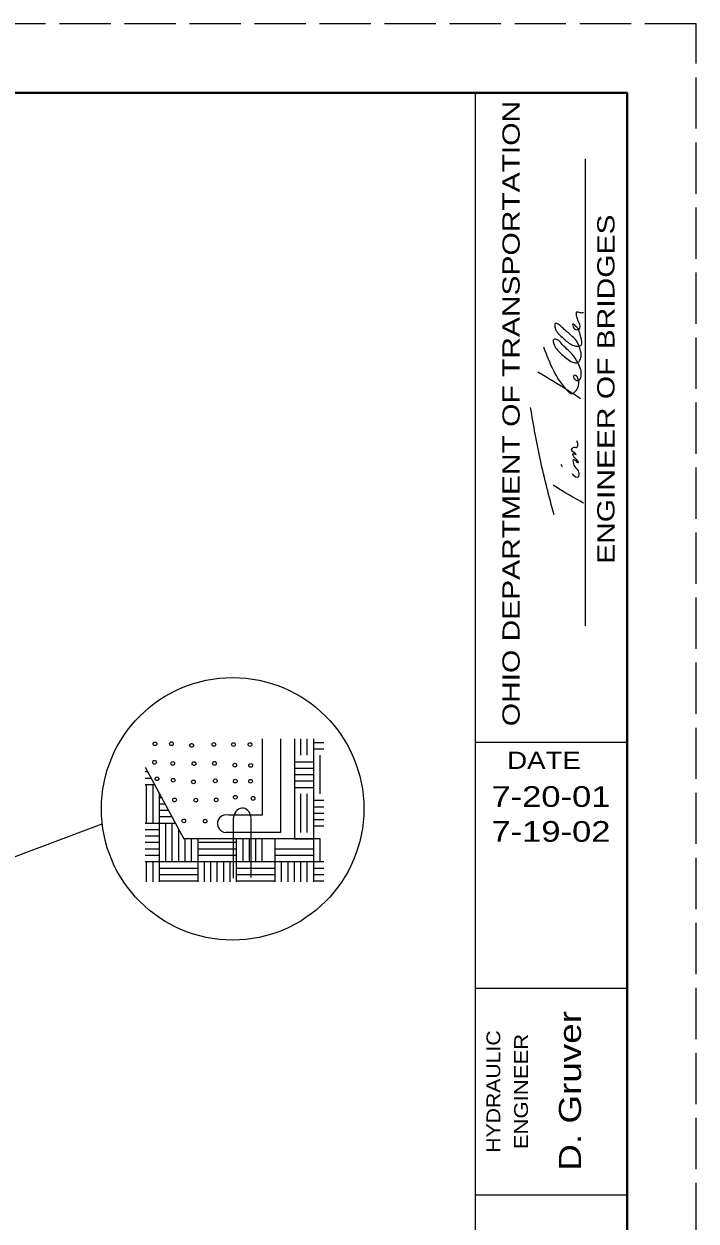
# Model space of a CAD drawing. Extents: x 1083.1 to 1117.1, y 719.4 to 741.4.
# Drawn here: x 1112.25 to 1117.13, y 732.67 to 741.35 of the extents above; entities that cross this region are included whole.
import ezdxf
from ezdxf.enums import TextEntityAlignment as Align

# ---------------------------------------------------------------- set-up
doc = ezdxf.new("R2010")
doc.units = 0
doc.header["$LTSCALE"] = 0.062
doc.linetypes.add('LONG_DASHED', pattern=[7.5, 6, -1.5])
doc.layers.add('1', color=7, linetype='Continuous', lineweight=13)

msp = doc.modelspace()

# ---------------------------------------------------------------- linework, layer by layer
at = {"layer": '1', "lineweight": 25}
for p, q in [((1085.12642, 740.85408), (1116.62642, 740.85408)), ((1115.52642, 719.85408), (1115.52642, 740.85408)), ((1116.62642, 740.85408), (1116.62642, 719.85408)), ((1116.62642, 736.13825), (1115.52642, 736.13825)), ((1108.8655, 734.06875), (1112.81717, 735.54867)), ((1113.7685, 735.58275), (1113.7685, 735.15425)), ((1113.89717, 735.15925), (1113.89717, 735.59258)), ((1116.62642, 734.35408), (1115.52642, 734.35408)), ((1116.62642, 732.85408), (1115.52642, 732.85408))]:
    msp.add_line(p, q, dxfattribs=at)
at = {"layer": '1'}
for p, q in [((1116.32517, 736.98508), (1116.32517, 740.37517)), ((1116.15767, 738.136), (1116.1475, 738.15525)), ((1113.97767, 736.16442), (1113.97767, 735.61058)), ((1114.112, 736.16442), (1114.112, 735.48542)), ((1114.212, 736.16442), (1114.212, 735.43958)), ((1114.25867, 736.04592), (1114.25867, 736.16442)), ((1114.30533, 736.04592), (1114.30533, 736.16442)), ((1114.352, 735.43958), (1114.352, 736.16442)), ((1114.352, 736.13925), (1114.42483, 736.13925)), ((1114.352, 736.09258), (1114.42483, 736.09258)), ((1114.39867, 735.76608), (1114.39867, 736.04592)), ((1113.12783, 735.95925), (1113.41, 735.43958)), ((1114.212, 735.99925), (1114.352, 735.99925)), ((1113.12783, 735.92708), (1113.14533, 735.92708)), ((1113.12783, 735.88042), (1113.17067, 735.88042)), ((1114.212, 735.95275), (1114.352, 735.95275)), ((1114.212, 735.90608), (1114.352, 735.90608)), ((1113.12783, 735.83375), (1113.196, 735.83375)), ((1113.13917, 735.69392), (1113.13917, 735.83375)), ((1113.18583, 735.69392), (1113.18583, 735.83375)), ((1114.212, 735.85942), (1114.352, 735.85942)), ((1114.212, 735.81275), (1114.352, 735.81275)), ((1113.13917, 735.55392), (1113.13917, 735.69392)), ((1113.18583, 735.55392), (1113.18583, 735.69392)), ((1113.2325, 735.12642), (1113.2325, 735.76642)), ((1113.2325, 735.74042), (1113.24667, 735.74042)), ((1113.2325, 735.69392), (1113.272, 735.69392)), ((1114.25867, 735.62625), (1114.25867, 735.76608)), ((1114.30533, 735.62625), (1114.30533, 735.76608)), ((1114.352, 735.71942), (1114.42483, 735.71942)), ((1113.2325, 735.64725), (1113.29733, 735.64725)), ((1113.97767, 735.61058), (1113.736, 735.61058)), ((1114.25867, 735.48625), (1114.25867, 735.62625)), ((1114.30533, 735.48625), (1114.30533, 735.62625)), ((1114.352, 735.67275), (1114.42483, 735.67275)), ((1114.352, 735.62625), (1114.42483, 735.62625)), ((1113.12783, 735.55392), (1113.348, 735.55392)), ((1113.2325, 735.60058), (1113.32267, 735.60058)), ((1113.27917, 735.27408), (1113.27917, 735.55392)), ((1113.32583, 735.27408), (1113.32583, 735.55392)), ((1114.352, 735.57958), (1114.42483, 735.57958)), ((1114.352, 735.53292), (1114.42483, 735.53292)), ((1113.12783, 735.50725), (1113.2325, 735.50725)), ((1113.12783, 735.46058), (1113.2325, 735.46058)), ((1113.3725, 735.27408), (1113.3725, 735.50875)), ((1113.41917, 735.27408), (1113.41917, 735.43958)), ((1113.46583, 735.27408), (1113.46583, 735.43958)), ((1113.51233, 735.12642), (1113.51233, 735.43958)), ((1114.112, 735.48542), (1113.71467, 735.48542)), ((1113.79233, 735.12642), (1113.79233, 735.43958)), ((1113.83883, 735.27408), (1113.83883, 735.43958)), ((1113.8855, 735.27408), (1113.8855, 735.43958)), ((1113.93217, 735.27408), (1113.93217, 735.43958)), ((1113.97883, 735.27408), (1113.97883, 735.43958)), ((1114.07217, 735.12642), (1114.07217, 735.43958)), ((1114.07217, 735.43358), (1114.07217, 735.43958)), ((1114.212, 735.43958), (1114.352, 735.43958)), ((1114.352, 735.12642), (1114.352, 735.43958)), ((1114.39867, 735.27408), (1114.39867, 735.43958)), ((1113.12783, 735.41408), (1113.2325, 735.41408)), ((1113.12783, 735.36742), (1113.2325, 735.36742)), ((1113.51233, 735.41408), (1113.65233, 735.41408)), ((1113.51233, 735.36742), (1113.65233, 735.36742)), ((1113.65233, 735.41408), (1113.79233, 735.41408)), ((1113.65233, 735.36742), (1113.79233, 735.36742)), ((1114.07133, 735.36742), (1114.352, 735.36742)), ((1113.12783, 735.32075), (1113.2325, 735.32075)), ((1113.12783, 735.27408), (1114.1265, 735.27408)), ((1113.13917, 735.13425), (1113.13917, 735.27408)), ((1113.18583, 735.13425), (1113.18583, 735.27408)), ((1113.51233, 735.32075), (1113.65233, 735.32075)), ((1113.559, 735.13425), (1113.559, 735.27408)), ((1113.60567, 735.13425), (1113.60567, 735.27408)), ((1113.65233, 735.32075), (1113.79233, 735.32075)), ((1113.65233, 735.13425), (1113.65233, 735.27408)), ((1113.699, 735.13425), (1113.699, 735.27408)), ((1113.74567, 735.13425), (1113.74567, 735.27408)), ((1114.075, 735.32075), (1114.352, 735.32075)), ((1114.11883, 735.13425), (1114.11883, 735.27408)), ((1114.1265, 735.27408), (1114.42483, 735.27408)), ((1114.1655, 735.13425), (1114.1655, 735.27408)), ((1114.212, 735.13425), (1114.212, 735.27408)), ((1114.25867, 735.13425), (1114.25867, 735.27408)), ((1114.30533, 735.13425), (1114.30533, 735.27408)), ((1113.2325, 735.22742), (1113.51233, 735.22742)), ((1113.2325, 735.18075), (1113.51233, 735.18075)), ((1113.79233, 735.22742), (1114.07217, 735.22742)), ((1113.79233, 735.18075), (1114.07217, 735.18075)), ((1114.352, 735.22742), (1114.42483, 735.22742)), ((1114.352, 735.18075), (1114.42483, 735.18075)), ((1113.13917, 735.12642), (1113.13917, 735.13425)), ((1113.18583, 735.12642), (1113.18583, 735.13425)), ((1113.2325, 735.13425), (1113.51233, 735.13425)), ((1113.559, 735.12642), (1113.559, 735.13425)), ((1113.60567, 735.12642), (1113.60567, 735.13425)), ((1113.65233, 735.12642), (1113.65233, 735.13425)), ((1113.699, 735.12642), (1113.699, 735.13425)), ((1113.74567, 735.12642), (1113.74567, 735.13425)), ((1113.79233, 735.13425), (1114.07217, 735.13425)), ((1114.11883, 735.12642), (1114.11883, 735.13425)), ((1114.1655, 735.12642), (1114.1655, 735.13425)), ((1114.212, 735.12642), (1114.212, 735.13425)), ((1114.25867, 735.12642), (1114.25867, 735.13425)), ((1114.30533, 735.12642), (1114.30533, 735.13425)), ((1114.352, 735.13425), (1114.42483, 735.13425))]:
    msp.add_line(p, q, dxfattribs=at)
at = {"layer": '1', "linetype": 'LONG_DASHED'}
msp.add_lwpolyline([(1083.12642, 719.35408), (1117.12642, 719.35408), (1117.12642, 741.35408), (1083.12642, 741.35408)], close=True, dxfattribs=at)
at = {"layer": '1', "lineweight": 40}
msp.add_lwpolyline([(1085.12642, 740.85408), (1116.62642, 740.85408), (1116.62642, 719.85408), (1085.12642, 719.85408)], close=True, dxfattribs=at)
msp.add_lwpolyline([(1085.12642, 740.85408), (1116.62642, 740.85408), (1116.62642, 719.85408), (1085.12642, 719.85408)], close=True, dxfattribs=at)
at = {"layer": '1'}
msp.add_lwpolyline([(1114.39867, 735.43958), (1114.1265, 735.43958), (1113.41, 735.43958)], dxfattribs=at)
at = {"layer": '1', "lineweight": 25}
msp.add_circle((1113.76333, 735.65742), 0.9524, dxfattribs=at)
at = {"layer": '1'}
msp.add_arc((1113.71653, 735.5495), 0.06411, 72.32209, 268.34559, dxfattribs=at)
for centre in [(1113.19987, 736.1296), (1113.31948, 736.12993), (1113.46608, 736.11794), (1113.62767, 736.12443), (1113.76977, 736.12343), (1113.88938, 736.12377), (1113.19671, 735.99484), (1113.32915, 735.98651), (1113.48307, 735.98518), (1113.63167, 735.98718), (1113.77927, 735.97418), (1113.89455, 735.97252), (1113.2147, 735.87557), (1113.33248, 735.86491), (1113.63783, 735.86025), (1113.78277, 735.85842), (1113.89338, 735.85709), (1113.47907, 735.85292), (1113.34214, 735.7215), (1113.49607, 735.72016), (1113.64466, 735.72216), (1113.78295, 735.74159), (1113.91163, 735.73309), (1113.40947, 735.5695), (1113.5634, 735.56816)]:
    msp.add_ellipse(centre, major_axis=(0.01346, 0), ratio=0.999895, dxfattribs=at)
at = {"layer": '1', "lineweight": 25}
msp.add_ellipse((1113.83308, 735.58119), major_axis=(0.00198, 0.08195), ratio=0.78812, start_param=4.8785287, end_param=7.8539922, dxfattribs=at)
at = {"layer": '1'}
for points in [[(1116.01825, 739.01108), (1116.20142, 738.68275), (1116.21658, 738.67217), (1116.22675, 738.67217), (1116.25867, 738.69583), (1116.27375, 738.73), (1116.26875, 738.78125), (1116.25183, 738.80308), (1116.23833, 738.80308), (1116.23658, 738.79008), (1116.24675, 738.77492), (1116.26025, 738.7665), (1116.27533, 738.7665), (1116.2905, 738.78808), (1116.29392, 738.80742), (1116.28367, 738.86275), (1116.20142, 738.98317), (1116.15592, 739.02783), (1116.119, 739.06242), (1116.09383, 739.06458), (1116.09558, 739.026), (1116.12075, 738.98725), (1116.188, 738.92492), (1116.23008, 738.8995), (1116.26375, 738.895), (1116.28708, 738.921), (1116.29392, 738.95517), (1116.28883, 738.98092), (1116.25867, 739.05408), (1116.22842, 739.08608), (1116.16783, 739.1395), (1116.13917, 739.16533), (1116.10567, 739.18058), (1116.10225, 739.15258), (1116.11233, 739.12675), (1116.1695, 739.06683), (1116.24017, 739.01958), (1116.29217, 739.02192), (1116.2905, 739.07958), (1116.27867, 739.1225), (1116.26533, 739.14825), (1116.25517, 739.159), (1116.23175, 739.174), (1116.2335, 739.15692), (1116.26875, 739.13542), (1116.28367, 739.14617), (1116.27058, 739.19983), (1116.262, 739.22775), (1116.25867, 739.24042), (1116.25867, 739.25325), (1116.25867, 739.26192), (1116.28367, 739.25975), (1116.30908, 739.25975)], [(1115.97942, 738.82883), (1116.20317, 738.69133), (1116.28883, 738.63567)], [(1116.09567, 737.79183), (1115.997, 738.18708), (1115.92575, 738.56942)], [(1116.22675, 738.09075), (1116.235, 738.08008), (1116.27217, 738.06717), (1116.27692, 738.09958), (1116.25183, 738.136), (1116.23658, 738.17225), (1116.23658, 738.1915), (1116.25183, 738.18525), (1116.262, 738.17442), (1116.27217, 738.17008), (1116.2485, 738.20225), (1116.23658, 738.21725), (1116.2335, 738.23458), (1116.25692, 738.228), (1116.2485, 738.23667), (1116.22333, 738.2645), (1116.2335, 738.27967), (1116.25025, 738.28167), (1116.25867, 738.27967), (1116.26875, 738.301), (1116.262, 738.32892)], [(1116.31083, 737.87625), (1116.10567, 737.99625), (1116.09008, 738.00667)]]:
    msp.add_spline(points, degree=3, dxfattribs=at)

# ---------------------------------------------------------------- texts
for s, height, width, p in [('OHIO DEPARTMENT OF TRANSPORTATION', 0.125, 1.3, (1115.84633, 738.52633)), ('ENGINEER OF BRIDGES', 0.125, 1.3, (1116.53467, 738.70312)), ('D. Gruver', 0.16, 1.25, (1116.2915, 733.61017)), ('HYDRAULIC', 0.1, 1.15, (1115.7055, 733.60517)), ('ENGINEER', 0.1, 1.2, (1115.90642, 733.60521))]:
    msp.add_text(s, height=height, rotation=90, dxfattribs=dict(at, width=width)).set_placement(p, align=Align.CENTER)
for s, height, width, p in [('DATE', 0.125, 1.2, (1116.02312, 735.94683)), ('7-20-01', 0.15, 1.25, (1116.07346, 735.67133)), ('7-19-02', 0.15, 1.25, (1116.07346, 735.41825))]:
    msp.add_text(s, height=height, dxfattribs=dict(at, width=width)).set_placement(p, align=Align.CENTER)

doc.saveas('drawing.dxf')
